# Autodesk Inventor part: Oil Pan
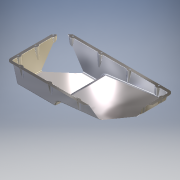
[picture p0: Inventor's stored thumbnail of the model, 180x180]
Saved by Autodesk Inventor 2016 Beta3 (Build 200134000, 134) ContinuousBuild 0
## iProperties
Shininess: 25.0
Length Units: 11269
Angle Units: 11279
Time Units: 11290
Mass Units: 11286
Length Display Precision: 3
Angle Display Precision: 2
Compacted: True
Company: Autodesk, Inc.
Created: 2000-11
Part Number: Oil Pan
Document SubType Name: Modeling
Designer: Autodesk, Inc.
Density: 1 g/cm^3
Mass: 268.575 g
Surface Area: 4246.09 cm^2
Volume: 268.575 cm^3
Material: Generic
Appearance: Metal-AL-6061 (Polished)
Density: 0.0
Volumn: 0.0
Area: 0.0
PropertySet Name: Model Information
Control State: 0
Master: False
Checked Out: False
Author: Autodesk, Inc.
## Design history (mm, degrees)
sketch "Sketch2"
  geometry: L1 (-254, 127)-(254, 127); L2 (254, 127)-(254, -127); L3 (254, -127)-(-254, -127); L4 (-254, -127)-(-254, 127); L5 (0, 0)-(0, -127); L6 (0, 0)-(-254, 0)
  constraints: 12 end point, 3 perpendicular, 2 midpoint, 2 parallel, 1 horizontal
  dimensions: "d0" = 508 distance of L2.end L3.end; "d1" = 254 distance of L1.end L2.end
extrude "Extrusion1" new body sketch "Sketch2" distance "d2" = 76.2; taper "d3" = 0 deg
sketch "Sketch3"
  geometry: L1 (-254, -127)-(-254, 127) reference; L2 (254, -127)-(-254, -127) reference; L3 (-254, 127)-(-50.8, 127); L4 (-50.8, 127)-(-50.8, -127); L5 (-50.8, -127)-(-254, -127); L6 (-254, -127)-(-254, 127)
  constraints: 8 end point, 2 parallel, 1 horizontal, 1 perpendicular, 1 point on line
  dimensions: "d4" = 203.2 distance of L1.end L3.end
extrude "Extrusion2" join sketch "Sketch3" distance "d5" = 38.1; taper "d6" = 0 deg
sketch "Sketch4"
  geometry: L1 (-254, -127)-(-254, 127) reference; L2 (-50.8, 127)-(-50.8, -127) reference; L3 (-50.8, -76.2)-(-254, -76.2); L4 (-50.8, -127)-(-254, -127) reference
  constraints: 2 end point, 2 point on line, 1 perpendicular
  dimensions: "d17" = 50.8 distance between parallel lines of L3 L4
split "Split1" sketch "Sketch4"
fillet "Fillet4" dims "d18" = 127
fillet "Fillet1" dims "d9" = 19.05
fillet "Fillet2" dims "d10" = 19.05
shell "Shell1" dims "d11" = 12.7
sketch "Sketch15" dims "d118" = 10, "d137" = 10
  geometry: L1 (-235.092, 127)-(235.092, 127) reference; L2 (-254, -108.092)-(-254, 108.092) reference; L3 (235.092, -127)-(-235.092, -127) reference; L4 (254, 108.092)-(254, -108.092) reference; L5 (247.5, 108.092)-(247.5, -108.092); L6 (235.092, -120.5)-(-235.092, -120.5); L7 (-247.5, -108.092)-(-247.5, 108.092); L8 (-235.092, 120.5)-(235.092, 120.5); L9 (-361.106, 0)-(361.106, 0) reference; L10 (-210.2, 120.5)-(-184.8, 120.5); L11 (-80.2, 120.5)-(-54.8, 120.5); L12 (49.8, 120.5)-(75.2, 120.5); L13 (179.8, 120.5)-(205.2, 120.5); L14 (-247.5, 12.7)-(-247.5, -12.7); L15 (-247.5, 92.7)-(-247.5, 67.3); L16 (-247.5, -92.7)-(-247.5, -67.3); A1 r 12.7 centre (-197.5, 120.5) between (-210.2, 120.5) and (-184.8, 120.5); A2 r 12.7 centre (-67.5, 120.5) between (-80.2, 120.5) and (-54.8, 120.5); A3 r 12.7 centre (62.5, 120.5) between (49.8, 120.5) and (75.2, 120.5); A4 r 12.7 centre (192.5, 120.5) between (179.8, 120.5) and (205.2, 120.5); A5 r 12.7 centre (-247.5, 0) between (-247.5, -12.7) and (-247.5, 12.7); A6 r 12.7 centre (-247.5, 80) between (-247.5, 67.3) and (-247.5, 92.7); A7 r 12.7 centre (-247.5, -80) between (-247.5, -92.7) and (-247.5, -67.3); 10 further points; 3 other entities
  constraints: 22 end point, 17 point on circle, 7 centre point, 7 coincident, 6 point on line, 5 collinear, 5 parallel, 5 symmetric about line, 1 horizontal, 1 midpoint, 1 vertical, 35 other
  dimensions: "d110" = 6.5 distance between parallel lines of L1 L8; "d111" = 50 distance from line of point (-197.5, 120.5) L7; "d112" = 12.7 radius of A1; "d115" = 130 distance of A1.centre A2.centre; "d121" = 12.7 radius of A5 (derived); "d129" = 120.5 vertical distance of point (-197.5, 120.5) point (-247.5, 0) (derived); "d134" = 80 distance of A5.centre A6.centre
extrude "Extrusion10" join sketch "Sketch15" stored distance "d130" = 10; taper "d131" = 0 deg
mirror "Mirror1"
extrude "Extrusion11" join sketch "Sketch15" stored distance "d139" = 10; taper "d140" = 0 deg
mirror "Mirror2"
shell "Shell5" dims "d91" = 1.27
fillet "Fillet10" dims "d52" = 3.81, "d102" = 5.099 (derived)
sketch "Sketch16"
  geometry: A1 r 12.7 centre (-247.5, 80) between (-239.705, 69.974) and (-239.705, 90.026) reference; A2 r 12.7 centre (-197.5, 120.5) between (-207.526, 112.705) and (-187.474, 112.705) reference; A3 r 12.7 centre (-67.5, 120.5) between (-77.526, 112.705) and (-57.474, 112.705) reference; A4 r 12.7 centre (62.5, 120.5) between (52.474, 112.705) and (72.526, 112.705) reference; A5 r 12.7 centre (192.5, 120.5) between (182.474, 112.705) and (202.526, 112.705) reference; A6 r 12.7 centre (247.5, 80) between (239.705, 90.026) and (239.705, 69.974) reference; A7 r 12.7 centre (247.5, 0) between (239.705, 10.026) and (239.705, -10.026) reference; A8 r 12.7 centre (247.5, -80) between (239.705, -69.974) and (239.705, -90.026) reference; A9 r 12.7 centre (192.5, -120.5) between (202.234, -112.343) and (182.766, -112.343) reference; A10 r 12.7 centre (62.5, -120.5) between (72.526, -112.705) and (52.474, -112.705) reference; A11 r 12.7 centre (-67.5, -120.5) between (-57.474, -112.705) and (-77.526, -112.705) reference; A12 r 12.7 centre (-197.5, -120.5) between (-187.474, -112.705) and (-207.526, -112.705) reference; A13 r 12.7 centre (-247.5, -80) between (-239.705, -90.026) and (-239.705, -69.974) reference; A14 r 12.7 centre (-247.5, 0) between (-239.705, -10.026) and (-239.705, 10.026) reference
hole "Hole4" sketch "Sketch16" at (-247.5, 0), (-247.5, 80), (-247.5, -80), (-197.5, 120.5), (-67.5, 120.5), (62.5, 120.5), (192.5, 120.5), (247.5, 80), (247.5, 0), (247.5, -80), (192.5, -120.5), (62.5, -120.5)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 diameter "d141" = 6.35; stored, may be unused: countersink angle "d145" = 90 deg, drill point angle "d147" = 118 deg; dims "d142" = 6, "d143" = 4, "d144" = 2, "d146" = 8
fillet "Fillet15" dims "d100" = 0.508, "d101" = 1.797 (derived)
sketch "Sketch14"
  geometry: L1 (158.973, 0)-(0, 0) reference; L2 (0, 16.586)-(158.973, 16.586) reference; C1 r 8.293 at (30.612, 8.293); C2 r 3.175 at (-24.388, 96.112) reference
  constraints: 2 tangent, 1 centre point
  dimensions: "d148" = 55 horizontal distance of C1.centre C2.centre
extrude "Extrusion9" join sketch "Sketch14" distance "d105" = 3.81; taper "d106" = 0 deg
fillet "Fillet13" dims "d64" = 1.905 (derived)
sketch "Sketch12"
  geometry: C1 r 7.168 at (0, 0); C2 r 6.388 at (0, 0) reference; 1 further point
  constraints: 1 centre point, 1 coincident
hole "Hole2" sketch "Sketch12" at (0, 0) diameter "d65" = 10.414; stored, may be unused: countersink angle "d68" = 60 deg, drill point angle "d70" = 118 deg; dims "d66" = 9.525, "d67" = 6.35, "d69" = 19.05, "d107" = 12.7
body "Solid1"
feature "FaceDraft1" dims angle "d7" = 20 deg
feature "FaceDraft5" dims angle "d16" = 3 deg
feature "FaceDraft4" dims angle "d15" = 7 deg
feature "FaceDraft7" dims angle "d42" = 7 deg
other parameters: "d73" = 12.7, "Thickness" = 1.289 [user parameter]
